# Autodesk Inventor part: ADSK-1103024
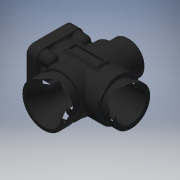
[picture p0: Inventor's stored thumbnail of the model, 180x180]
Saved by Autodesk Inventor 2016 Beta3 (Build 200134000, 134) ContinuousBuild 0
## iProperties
Shininess: 11.0
Length Units: 11272
Angle Units: 11279
Time Units: 11290
Mass Units: 11286
Length Display Precision: 4
Angle Display Precision: 2
Compacted: True
Created: 2000-08
Part Number: ADSK-1103024
Document SubType Name: Modeling
Description: CARB HOUSING
Mass: 7.38977 g
Surface Area: 30.8 cm^2
Volume: 2.72685 cm^3
Density: 2.71 g/cm^3
Material: Aluminum-6061
Appearance: Black
Density: 0.0
Volumn: 0.0
Area: 0.0
PropertySet Name: Model Information
Control State: 0
Master: False
Checked Out: False
Author: Autodesk, Inc.
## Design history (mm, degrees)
node "Extrusion1" dims "d1" = 15.24, "d2" = 0
  sketch "Sketch3"
    geometry: C1 r 6.35 at (6.191, -11.43)
    constraints: 1 centre point
    dimensions: "d0" = 12.7 diameter of C1
workaxis "Work Axis1"
workplane "Work Plane1"
node "Extrusion2" dims "d5" = 19.05, "d6" = 0
  sketch "Sketch4"
    geometry: L1 (-6.35, 15.24)-(6.35, 15.24) reference; L2 (0, -3.048)-(0, 18.288) reference; C1 r 6.35 at (0, 7.62)
    constraints: 1 centre point, 1 midpoint
    dimensions: "d4" = 12.7 diameter of C1; "d23" = 1.27 distance edge to line of C1 L1
node "Extrusion3" dims "d8" = 2.0955, "d9" = 0
  sketch "Sketch5"
    geometry: C1 r 5.715 at (6.191, -11.43); A1 r 6.35 centre (6.191, -11.43) between (12.541, -11.43) and (-0.159, -11.43) reference
    constraints: 1 centre point, 1 coincident
    dimensions: "d7" = 0.635 radial gap between concentric circles of A1 C1
node "Extrusion4" dims "d10" = 3.175, "d11" = 0
  sketch "Sketch6"
    geometry: A1 r 6.35 centre (0, 0) between (6.35, 0) and (-6.35, 0) reference; A2 r 6.35 centre (0, 0) between (-6.35, 0) and (6.35, 0) reference
node "Extrusion5" dims "d13" = 3.175, "d14" = 0
  sketch "Sketch7"
    geometry: L1 (-6.985, 6.985)-(6.985, 6.985); L2 (6.985, 6.985)-(6.985, -6.985); L3 (6.985, -6.985)-(-6.985, -6.985); L4 (-6.985, -6.985)-(-6.985, 6.985); C1 r 6.35 at (0, 0) reference; C2 r 6.985 at (0, 0)
    constraints: 8 end point, 4 tangent, 2 parallel, 1 centre point, 1 coincident, 1 horizontal, 1 perpendicular
    dimensions: "d12" = 0.635 radial gap between concentric circles of C1 C2
node "Fillet1" dims "d15" = 2.0955
workaxis "Work Axis2"
workplane "Work Plane2"
node "Revolution1" dims "d17" = 90 deg
  sketch "Sketch8"
    geometry: L1 (-13.652, 0)-(15.24, 0) reference; L2 (-9.525, -6.35)-(0, -6.35) reference; L3 (0, -6.35)-(7.938, -6.35) reference; L4 (-1.675, -4.053)-(-3.549, -6.35); L5 (-3.549, -6.35)-(1.623, -10.571); L6 (1.623, -10.571)-(3.498, -8.274); L7 (3.498, -8.274)-(-1.675, -4.053)
    constraints: 8 end point, 2 parallel, 1 perpendicular, 1 point on line
node "Extrusion6" dims "d19" = 3.175, "d20" = 0
  sketch "Sketch9"
    geometry: C1 r 3.599 at (0, 0); A1 r 2.964 centre (0, 0) between (-2.964, 0) and (2.964, 0); A2 r 2.964 centre (0, 0) between (-1.31, 2.659) and (1.31, 2.659) reference
    constraints: 2 centre point, 2 point on circle, 1 coincident, 1 concentric
    dimensions: "d18" = 0.635 radial gap between concentric circles of C1 A1
node "Fillet4" dims "d24" = 0.8128
node "Fillet5" dims "d25" = 0.8128
node "Fillet16" dims "d78" = 0.8128
node "Fillet17" dims "d79" = 0.8128
node "Fillet18" dims "d80" = 0.381
node "Extrusion12" dims "d50" = 5.08, "d51" = 0
  sketch "Sketch16"
    geometry: C1 r 6.35 at (0, 0) reference; C2 r 5.006 at (0, 0)
    constraints: 1 centre point, 1 coincident
node "Hole1" dims "d28" = 6.35, "d29" = 10.795, "d30" = 6.35, "d31" = 60 deg, "d32" = 19.05, "d33" = 118 deg
  sketch "Sketch10"
    geometry: C1 r 6.35 at (0, 0) reference
node "Extrusion7" dims "d35" = 0.635, "d36" = 0
  sketch "Sketch11"
    geometry: C1 r 6.35 at (0, 0) reference; C2 r 4.445 at (0, 0)
    constraints: 1 centre point, 1 coincident
    dimensions: "d81" = 8.89 diameter of C2
node "Extrusion8" dims "d38" = 0.635, "d39" = 0
  sketch "Sketch12"
    geometry: C1 r 1.048 at (0, 0); A1 r 1.531 centre (0, 0) between (-1.514, 0.226) and (1.514, 0.226); A2 r 2.583 centre (0, 0) between (-2.16, 1.416) and (2.16, 1.416) reference; A3 r 2.787 centre (0, 0) between (0.61, 2.719) and (-0.61, 2.719) reference; 4 further points
    constraints: 2 centre point, 2 coincident, 2 point on circle, 5 other
    dimensions: "d37" = 2.0955 diameter of C1
node "Extrusion9" dims "d41" = 1.27, "d42" = 0
  sketch "Sketch13"
    geometry: C1 r 4.445 at (0, 0) reference; C2 r 2.349 at (0, 0)
    constraints: 1 centre point, 1 coincident
    dimensions: "d40" = 2.0955 radial gap between concentric circles of C1 C2
node "Extrusion10" dims "d43" = 0, "d44" = 2.54
  sketch "Sketch14"
    geometry: C1 r 5.08 at (6.191, -11.112); C2 r 6.35 at (6.191, -11.112) reference; 2 further points
    constraints: 1 centre point, 1 concentric, 2 other
    dimensions: "d46" = 1.27 radial gap between concentric circles of C2 C1
node "Extrusion11" dims "d47" = 1.27, "d48" = 0
  sketch "Sketch15"
    geometry: C1 r 4.445 at (0, 0) reference; C2 r 5.715 at (0, 0); C3 r 5.08 at (0, 0) reference
    constraints: 1 centre point, 1 concentric
    dimensions: "d49" = 0.635 radial gap between concentric circles of C2 C3
node "Chamfer1" dims "d52" = 0.381, "d53" = 0.381, "d82" = 45 deg
node "Extrusion13" dims "d58" = 1.27, "d59" = 30 deg
  sketch "Sketch17"
    geometry: L1 (6.35, -3.302)-(15.875, -3.302); L2 (15.875, -3.302)-(15.875, -6.477); L3 (15.875, -6.477)-(6.35, -6.477); L4 (6.35, -6.477)-(6.35, -3.302); L5 (24.765, -4.889)-(-4.128, -4.889) reference; L6 (11.113, 12.929)-(11.113, -22.898) reference
    constraints: 8 end point, 2 parallel, 1 horizontal, 1 perpendicular
    dimensions: "d54" = 3.175 distance of L1.end L2.end; "d55" = 9.525 distance of L2.end L3.end; "d56" = 4.7625 distance between parallel lines of L6 L2 (= 0.5 x d55); "d57" = 1.5875 distance between parallel lines of L1 L5 (= 0.5 x d54)
node "Fillet8" dims "d60" = 0.381
node "Fillet9" dims "d61" = 0.381
node "Extrusion14" dims "d62" = 0.762, "d63" = 0
  sketch "Sketch18"
    geometry: L1 (6.79, -3.742)-(15.435, -3.742); L2 (15.435, -3.742)-(15.435, -6.037); L3 (15.435, -6.037)-(6.79, -6.037); L4 (6.79, -6.037)-(6.79, -3.742); 4 further points; 2 other entities
    constraints: 8 end point, 2 parallel, 1 horizontal, 1 perpendicular, 2 other
node "Fillet10" dims "d64" = 0.127
node "Extrusion15" dims "d71" = 6.731, "d72" = -5 deg
  sketch "Sketch20"
    geometry: A1 r 2.096 centre (4.889, 4.889) between (6.985, 4.889) and (4.889, 6.985) reference; A2 r 2.096 centre (-4.889, 4.889) between (-4.889, 6.985) and (-6.985, 4.889) reference; A3 r 2.096 centre (-4.889, -4.889) between (-6.985, -4.889) and (-4.889, -6.985) reference; A4 r 2.095 centre (4.889, -4.889) between (4.889, -6.985) and (6.985, -4.889) reference; 4 further points
    constraints: 4 coincident, 3 vertical alignment, 1 horizontal alignment, 8 other
node "Hole2" dims "d65" = 2.013, "d66" = 9.525, "d67" = 6.35, "d68" = 60 deg, "d69" = 5.08, "d70" = 118 deg
  sketch "Sketch19"
    geometry: A1 r 2.095 centre (4.889, -4.889) between (4.889, -6.985) and (6.985, -4.889) reference; A2 r 2.096 centre (4.889, 4.889) between (6.985, 4.889) and (4.889, 6.985) reference; A3 r 2.096 centre (-4.889, 4.889) between (-4.889, 6.985) and (-6.985, 4.889) reference; A4 r 2.096 centre (-4.889, -4.889) between (-6.985, -4.889) and (-4.889, -6.985) reference
node "Fillet11" dims "d73" = 0.127
node "Fillet12" dims "d74" = 1.27
node "Fillet14" dims "d76" = 0.381
node "Fillet15" dims "d77" = 0.381
body "Solid1"
other parameters: "d3" = 90 deg, "d16" = 0
